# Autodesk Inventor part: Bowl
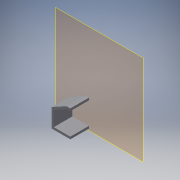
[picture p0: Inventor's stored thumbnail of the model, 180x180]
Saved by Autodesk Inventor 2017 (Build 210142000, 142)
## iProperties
Created: 2017-05
Part Number: Bowl
Material: Generic
Document SubType Name: Modeling
Designer: 1460374
Density: 1 g/cm^3
Appearance: Default
Author: 1460374
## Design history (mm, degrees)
workplane "Work Plane1"
sketch "Sketch1"
  geometry: L1 (6.014, 0)-(6.014, 25.4); L2 (6.014, 25.4)-(28.554, 37.872); L3 (28.554, 37.872)-(34.273, 37.872); L4 (6.014, 0)-(34.273, 0); L5 (34.273, 41.769)-(27.547, 41.769); L6 (27.547, 41.769)-(2.117, 27.698); L7 (2.117, 27.698)-(2.117, -3.897); L8 (2.117, -3.897)-(34.273, -3.897); L9 (34.273, 41.769)-(34.273, 37.872); L10 (34.273, 0)-(34.273, -3.897); 1 further point
  constraints: 20 end point, 2 perpendicular, 2 vertical, 1 collinear, 1 horizontal, 3 other
  dimensions: "d0" = 25.4 distance of L1.start L1.end
extrude "Extrusion1" new body sketch "Sketch1" distance "d1" = 31.75; taper "d2" = 0 deg
workplane "Work Plane2"
sketch "Sketch2"
  geometry: L1 (11.995, 32.404)-(11.995, 0.809) reference; L2 (2.716, 16.606)-(11.995, 16.606); C1 r 1.687 at (8.995, 23.742); C2 r 1.687 at (8.995, 9.47); 1 further point
  constraints: 2 centre point, 2 end point, 1 midpoint, 1 symmetric about line, 3 other
extrude "Extrusion2" join sketch "Sketch2" stored distance "d6" = 23.8125; taper "d7" = 0 deg
sketch "Sketch3"
  geometry: L1 (0, 25.4)-(-31.75, 25.4) reference; L2 (-31.75, 0)-(-26.025, 0); L3 (-26.025, 0)-(-26.025, 25.4); L4 (-26.025, 25.4)-(-31.75, 25.4); L5 (-31.75, 25.4)-(-31.75, 0); 1 further point
  constraints: 8 end point, 2 parallel, 1 horizontal, 1 perpendicular, 1 point on line
extrude "Extrusion3" join sketch "Sketch3" stored distance "d8" = 28.575; taper "d9" = 0 deg
sketch "Sketch4"
  geometry: L1 (0, 0)-(0, -5.725) reference; L2 (0, -5.725)-(0, 0); L3 (0, 0)-(28.259, 0); L4 (28.259, -5.725)-(28.259, 0) reference; L5 (28.259, 0)-(28.259, -5.725); L6 (28.259, -5.725)-(0, -5.725); 1 further point
  constraints: 8 end point, 2 point on line, 1 collinear, 1 perpendicular
extrude "Extrusion4" join sketch "Sketch4" distance "d10" = 14.2875; taper "d11" = 0 deg
sketch "Sketch5"
  geometry: L1 (6.014, 29.854)-(23.786, 39.688) reference; L2 (6.014, 39.688)-(23.786, 39.688) reference; L3 (23.786, 39.688)-(6.014, 39.688); L4 (6.014, 29.854)-(6.014, 39.688) reference; L5 (6.014, 39.688)-(6.014, 29.854); 1 further point
  constraints: 4 end point, 2 collinear
extrude "Extrusion5" cut sketch "Sketch5" distance "d12" = 9.525; taper "d13" = 0 deg
sketch "Sketch6"
  geometry: L1 (0, 3.897)-(-26.025, 3.897) reference; L2 (-26.025, 3.897)-(-26.025, 0); L3 (0, 0)-(-31.75, 0) reference; L4 (0, 0)-(0, 3.897) reference; L5 (0, 3.897)-(0, 0); L6 (0, 0)-(-26.025, 0)
  constraints: 6 end point, 1 collinear, 1 perpendicular, 1 point on line, 1 vertical
extrude "Extrusion6" cut sketch "Sketch6" distance "d14" = 20.6375; taper "d15" = 0 deg
body "Solid1"
